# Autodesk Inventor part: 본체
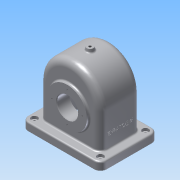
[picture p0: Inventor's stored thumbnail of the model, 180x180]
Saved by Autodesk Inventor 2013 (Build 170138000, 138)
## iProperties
Created: 2016-10
Part Number: 본체
Material: 알루미늄 6061
Document SubType Name: Modeling
Designer: user
Density: 2.71 g/cm^3
Mass: 1140.15 g
Surface Area: 1193.68 cm^2
Volume: 420.719 cm^3
Author: user
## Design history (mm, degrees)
sketch "스케치1"
  geometry: L1 (75, -55)-(-75, -55); L2 (-75, -55)-(-75, 55); L3 (-75, 55)-(75, 55); L4 (75, 55)-(75, -55); L5 (75, -55)-(-75, 55); L6 (-75, -55)-(75, 55); 1 further point
  constraints: 12 end point, 2 midpoint, 2 parallel, 1 horizontal, 1 perpendicular
  dimensions: "d0" = 150 distance of L1.start L1.end; "d2" = 110 distance of L3.end L1.start
extrude "돌출1" new body sketch "스케치1" distance "d3" = 15; taper "d4" = 0 deg
sketch "스케치2"
  geometry: L1 (-75.646, 80)-(75.646, 80); L2 (-75, 0)-(75, 0) reference; L3 (-58, 80)-(-58, 0); L4 (58, 80)-(58, 0); L5 (-58, 0)-(58, 0); A1 r 58 centre (0, 80) between (-58, 80) and (58, 80); 3 further points
  constraints: 8 end point, 4 point on line, 2 midpoint, 2 perpendicular, 2 point on circle, 2 tangent, 1 centre point, 1 coincident, 1 collinear, 1 horizontal, 1 vertical alignment
  dimensions: "d5" = 80 distance between parallel lines of L2 L1; "d6" = 116 diameter of A1
extrude "돌출2" join sketch "스케치2" stored distance "d7" = 77; taper "d8" = 0 deg
sketch "스케치3"
  geometry: L1 (75, 0)-(-75, 0) reference; C1 r 37.5 at (0, 65); 2 further points
  constraints: 1 centre point, 1 midpoint, 1 vertical alignment
  dimensions: "d12" = 75 diameter of C1; "d14" = 65 distance from line of L1 C1.centre
extrude "돌출3" join sketch "스케치3" distance "d15" = 5; taper "d16" = 0 deg
sketch "스케치4"
  geometry: L1 (75, 0)-(-75, 0) reference; C1 r 31 at (0, 65); 2 further points
  constraints: 1 centre point, 1 midpoint, 1 vertical alignment
  dimensions: "d17" = 62 diameter of C1; "d19" = 65 distance from line of L1 C1.centre
extrude "돌출4" join sketch "스케치4" distance "d20" = 10; taper "d21" = 0 deg
sketch "스케치7"
  geometry: L1 (-64.353, 113.349)-(56.669, 113.349); L2 (-6, 144)-(6, 144); L3 (6, 144)-(11.405, 113.349); L4 (-6, 144)-(-11.405, 113.349); L5 (-75, 0)-(75, 0) reference; L6 (0, 144)-(0, 113.349); 1 further point
  constraints: 10 end point, 3 point on line, 1 horizontal, 1 midpoint, 1 parallel, 1 perpendicular, 1 vertical alignment
  dimensions: "d27" = 144 distance between parallel lines of L5 L2; "d28" = 100 deg angle of L4 L1; "d29" = 100 deg angle of L1 L3; "d30" = 113.34911 distance between parallel lines of L5 L1; "d31" = 12 distance of L2.start L2.end
revolve "회전1" sketch "스케치7" stored, may be unused: angle "d32" = 90 deg
sketch "스케치10"
  geometry: L1 (-58, 15)-(58, 15) reference; L2 (-58, 15)-(-58, 80) reference; L3 (58, 80)-(58, 15) reference; L4 (-52, 80)-(-52, 0); L5 (52, 80)-(52, 0); L6 (52, 0)-(-52, 0); C1 r 31 at (0, 65) reference; A1 r 58 centre (0, 80) between (58, 80) and (-58, 80) reference; A2 r 52 centre (0, 80) between (-52, 80) and (52, 80); 1 further point
  constraints: 6 end point, 2 perpendicular, 2 point on circle, 2 tangent, 1 centre point, 1 coincident, 1 parallel
  dimensions: "d40" = 104 diameter of A2
extrude "돌출6" cut sketch "스케치10" stored distance "d43" = 67; taper "d44" = 0 deg
sketch "스케치12"
  geometry: L1 (102.5, 43.5)-(27.5, 43.5) reference; L2 (34, -48.5)-(96, -48.5) reference; L3 (132, -33.5)-(132, 33.5) reference; L4 (138, 38.5)-(80, 38.5) reference; L5 (132, 33.5)-(80, 33.5) reference; L6 (65, 43.5)-(65, -48.5); L7 (65, 19.5)-(93, 19.5); L8 (93, 19.5)-(104.747, 33.5); L9 (104.747, 33.5)-(65, 33.5); 1 further point
  constraints: 8 end point, 3 point on line, 2 midpoint, 2 perpendicular
  dimensions: "d45" = 56 diameter of L7.end L6; "d47" = 50 deg angle of L7 L8; "d110" = 24 distance between parallel lines of L7 L1
revolve "회전2" sketch "스케치12" stored, may be unused: angle "d50" = 90 deg
sketch "스케치13"
  geometry: C1 r 37.5 at (0, 0) reference; 1 further point
hole "구멍1" sketch "스케치13" at (0, 0) diameter "d51" = 40; stored, may be unused: countersink angle "d55" = 90 deg, drill point angle "d57" = 118 deg; dims "d52" = 6, "d53" = 4, "d54" = 2, "d56" = 8
fillet "모깎기1" dims "d58" = 8
chamfer "모따기1" distance "d59" = 1; stored, may be unused: second distance "d60" = 2, angle "d61" = 45 deg
fillet "모깎기2" dims "d62" = 3
fillet "모깎기3" dims "d63" = 13
sketch "스케치14" dims "d64" = 58
  geometry: C1 r 21 at (0, 0) reference; 3 further points
  constraints: 1 coincident, 1 vertical alignment, 2 other
hole "구멍2" sketch "스케치14" at (0, 29) diameter "d66" = 2.459; stored, may be unused: countersink angle "d70" = 90 deg, drill point angle "d72" = 118 deg; dims "d67" = 6, "d68" = 4, "d69" = 2, "d71" = 8
sketch "스케치15" dims "d76" = 52
  geometry: C1 r 21 at (0, 0) reference; 3 further points
  constraints: 1 coincident, 1 vertical alignment, 2 other
hole "구멍3" sketch "스케치15" at (0, 26) diameter "d78" = 2.459; stored, may be unused: countersink angle "d82" = 90 deg, drill point angle "d84" = 118 deg; dims "d79" = 6, "d80" = 4, "d81" = 2, "d83" = 8
fillet "모깎기4" dims "d88" = 3
fillet "모깎기5" dims "d89" = 3
fillet "모깎기6" dims "d90" = 12
fillet "모깎기7" dims "d91" = 3
sketch "스케치18"
  geometry: C1 r 6 at (0, 0) reference
hole "구멍4" sketch "스케치18" at (0, 0) diameter "d92" = 4.459; stored, may be unused: countersink angle "d96" = 90 deg, drill point angle "d98" = 118 deg; dims "d93" = 6, "d94" = 4, "d95" = 2, "d97" = 8
sketch "스케치19"
  geometry: A1 r 9 centre (63, -43) between (63, -52) and (72, -43) reference; A2 r 9 centre (63, 43) between (72, 43) and (63, 52) reference; A3 r 9 centre (-63, 43) between (-63, 52) and (-72, 43) reference; A4 r 9 centre (-63, -43) between (-72, -43) and (-63, -52) reference; 1 further point
hole "구멍5" sketch "스케치19" at (-63, 43), (-63, -43), (63, -43), (63, 43) diameter "d99" = 5; stored, may be unused: countersink angle "d103" = 90 deg, drill point angle "d105" = 118 deg; dims "d100" = 6, "d101" = 12, "d102" = 5, "d104" = 8
sketch "스케치20"
  geometry: L1 (-13, 0)-(-13, -62) reference; L2 (68.5, -80)-(-17.5, -80) reference; 2 further points
  constraints: 1 other
  dimensions: "d106" = 40 distance from line of L2 point (25.5, -40); "d107" = 38.5 distance from line of L1 point (25.5, -40)
feature "엠보싱1" sketch "스케치20" dims "d0" = 150, "d2" = 110, "d108" = 0.5, "d109" = 0
node "솔리드1"
pattern_circular "원형 패턴1" dims angle "d74" = 360 deg
pattern_circular "원형 패턴2" dims angle "d86" = 360 deg
node "투영된 루프1"
